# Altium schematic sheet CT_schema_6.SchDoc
size 278 x 170 mm
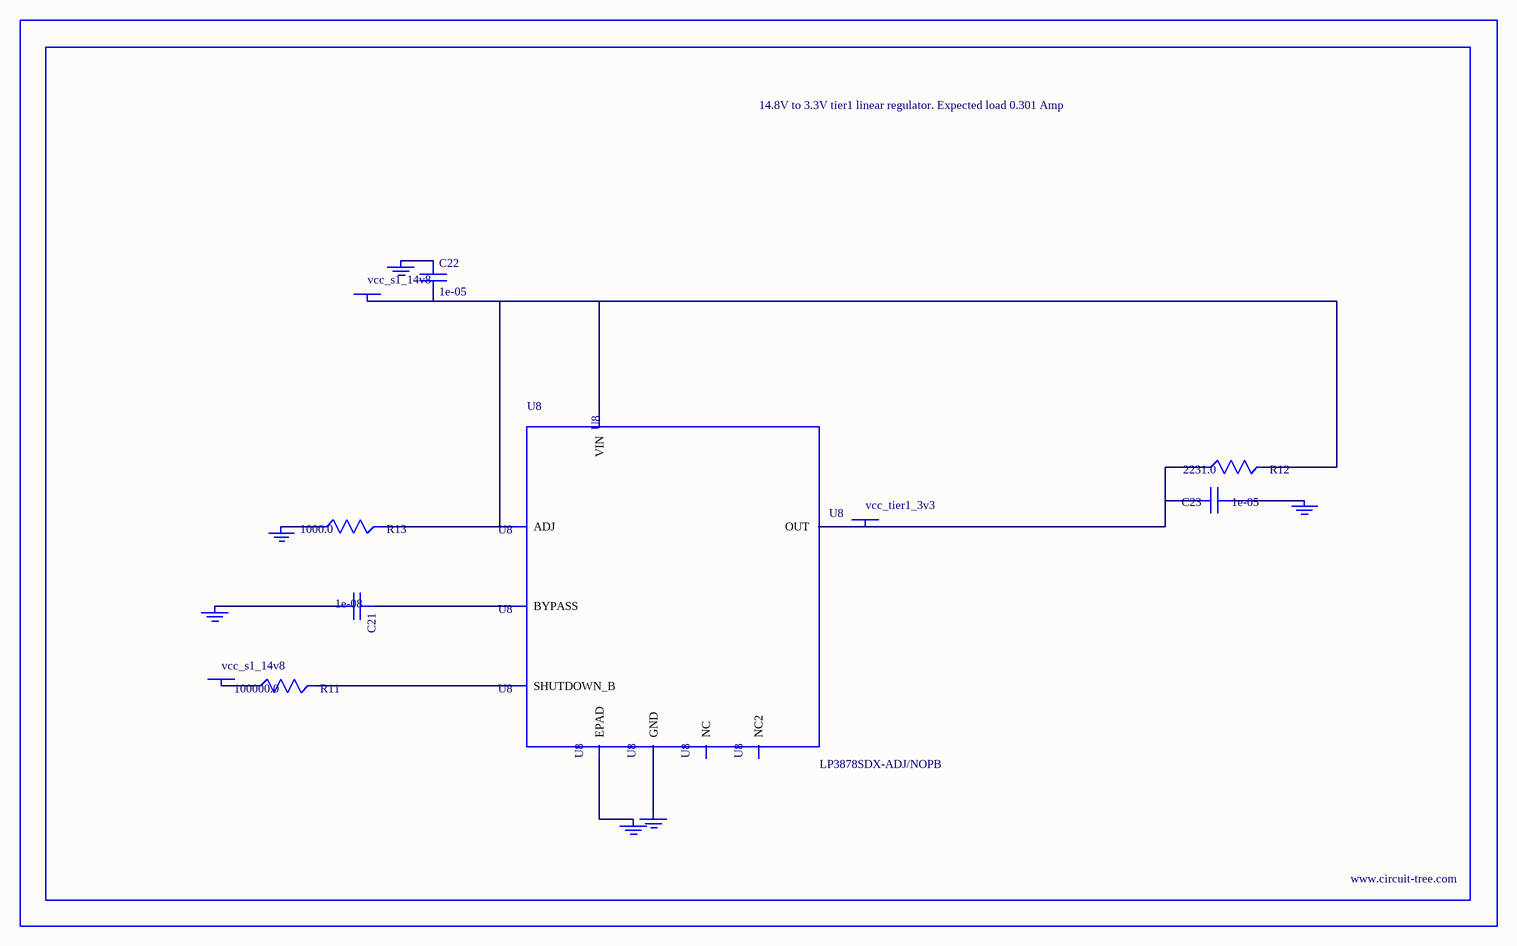
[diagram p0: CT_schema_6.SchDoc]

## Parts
BORDER5  (no value)
C21  1e-08  [C0402]
C22  1e-05  [C1210]
C23  1e-05  [C1210]
GND_INSTANCE_5_0  (no value)
GND_INSTANCE_5_1  (no value)
GND_INSTANCE_5_2  (no value)
GND_INSTANCE_5_3  (no value)
GND_INSTANCE_5_4  (no value)
GND_INSTANCE_5_5  (no value)
POWER_INSTANCE_5_0  vcc_s1_14v8
POWER_INSTANCE_5_1  vcc_s1_14v8
POWER_INSTANCE_5_2  vcc_tier1_3v3
R11  100000.0  [R0603]
R12  2231.0  [R0603]
R13  1000.0  [R0603]
U8  LP3878SDX-ADJ/NOPB  [WSON-8]

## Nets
NetC21_1: C21.1 U8.1(BYPASS)
NetC21_2: C21.2 GND_INSTANCE_5_0.0(GND)
NetC22_1: C22.1 GND_INSTANCE_5_1.0(GND)
NetC22_2: C22.2 POWER_INSTANCE_5_0.0(PWR) R12.2 R13.2 U8.4(VIN) U8.6(ADJ)
NetC23_1: C23.1 GND_INSTANCE_5_2.0(GND)
NetC23_2: C23.2 POWER_INSTANCE_5_2.0(PWR) R12.1 U8.5(OUT)
NetGND_INSTANCE_5_3_0: GND_INSTANCE_5_3.0(GND) R13.1
NetGND_INSTANCE_5_4_0: GND_INSTANCE_5_4.0(GND) U8.PAD(EPAD)
NetGND_INSTANCE_5_5_0: GND_INSTANCE_5_5.0(GND) U8.3(GND)
NetPOWER_INSTANCE_5_1_0: POWER_INSTANCE_5_1.0(PWR) R11.1
NetR11_2: R11.2 U8.8(SHUTDOWN_B)

Not connected (* = marked no-connect by the designer): U8 2(NC) 7(NC2)

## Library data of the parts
BORDER5 = BORDER_PAGE5
C21 = C0402C103K3RAC
C22 = C1210C106K5PACTU
C23 = GRM32DR61E106MA12L
GND_INSTANCE_5_0-GND_INSTANCE_5_5 = GND
POWER_INSTANCE_5_0-POWER_INSTANCE_5_2 = PWR
R11 = RC0603JR-07100KL
R12 = R12
R13 = RC0603JR-071KL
